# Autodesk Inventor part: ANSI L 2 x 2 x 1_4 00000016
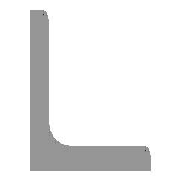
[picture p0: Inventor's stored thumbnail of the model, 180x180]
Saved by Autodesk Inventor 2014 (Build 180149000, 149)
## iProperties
IsCustomPart: 1
Created: 2007-02
Part Number: ANSI L 2 x 2 x 1_4 00000016
Material: Steel, Mild
Document SubType Name: Modeling
Standard: AISC
Designer: Autodesk, Inc.
Size Designation: L 2 x 2 x 1/4
Stock Number: L 2 x 2 x 1/4
Density: 7.86 g/cm^3
Description: Angle Steel
Standards Organization: ANSI
Language: en-US
Categories: <MemberInstance><Categories><Category DisplayName="Structural Shapes" InternalName="089c4875-fa83-4c05-b084-43b9cc11f5ed" Mnemonic="GRDR"><CategoryParameter Dis
Mass: 1510.44 g
Surface Area: 652.682 cm^2
Volume: 192.168 cm^3
Appearance: Steel
_FrameMemberDoc: Frame Member File
_Version: 15.0.0
_CCFamilyMember: 11
_CCFamilyDisplayName: ANSI L (Equal angles) - Angle Steel
G_L: 14.750 in
G_W: 2.000 in
G_H: 2.000 in
+8C4DC5A2-1CB2-4683-A8ED-186AF0FDBA7E+CUTDETAIL1: Notch
+BEC1791F-D03F-4A56-8F25-61346F2A3048+CUTDETAIL2: Notch
Author: Autodesk, Inc.
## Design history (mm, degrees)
node "Start plane"
node "End plane"
sketch "Sketch"
  geometry: L1 (50.8, 0)-(0, 0); L2 (0, 0)-(0, 50.8); L3 (0, 50.8)-(3.302, 50.8); L4 (6.35, 47.752)-(6.35, 12.7); L5 (12.7, 6.35)-(47.752, 6.35); L6 (50.8, 3.302)-(50.8, 0); L7 (0, -11.041)-(0, 31.538); L8 (-11.041, 0)-(31.538, 0); L9 (0, 63.926)-(0, -23.536) reference; L10 (-23.536, 0)-(63.926, 0) reference; A1 r 6.35 centre (12.7, 12.7) between (6.35, 12.7) and (12.7, 6.35); A2 r 3.048 centre (3.302, 47.752) between (6.35, 47.752) and (3.302, 50.8); A3 r 3.048 centre (47.752, 3.302) between (50.8, 3.302) and (47.752, 6.35); 3 further points
  constraints: 16 end point, 6 point on circle, 6 point on line, 6 tangent, 4 parallel, 3 centre point, 2 collinear, 1 equal radius, 1 horizontal, 1 perpendicular
  dimensions: "d0" = 50.8 distance between parallel lines of L6 L2 (= G_H); "d1" = 50.8 distance between parallel lines of L3 L1 (= G_H); "d2" = 6.35 distance between parallel lines of L2 L4 (= G_T); "d3" = 6.35 distance between parallel lines of L1 L5 (= G_T); "d10" = 0 distance between parallel lines of L7 L2 (computed from ex); "d11" = 0 distance between parallel lines of L8 L1 (computed from d10); "d14" = 6.35 radius of A1 (= G_IR); "d15" = 3.048 radius of A2 (= G_ER)
extrude "Body" new body sketch "Sketch" stored distance "d4" = 374.65 (= G_L); taper "d5" = 0 deg
node "Driven Length"
  sketch "Sketch5"
    geometry: L1 (0, 0)-(10, 0) reference
    constraints: 2 end point, 1 horizontal
  workplane "Work Plane7"
  sketch "Sketch6"
    geometry: L1 (-2, 0)-(12, 0) reference; L2 (-2, 374.65)-(12, 374.65) reference
    dimensions: "d21" = 374.65 distance between parallel lines of L1 L2 (derived)
workplane "Work Plane3"
workplane "Work Plane4"
workplane "Work Plane5"
workplane "Work Plane6"
workplane "Work Plane8"
workplane "Work Plane9"
body "Solid1"
sketch "Sketch_3"
  geometry: L1 (50.8, 0)-(0, 0); L2 (0, 0)-(0, 50.8); L3 (0, 50.8)-(3.302, 50.8); L4 (6.35, 47.752)-(6.35, 12.7); L5 (12.7, 6.35)-(47.752, 6.35); L6 (50.8, 3.302)-(50.8, 0); A1 r 3.048 centre (3.302, 47.752) between (6.35, 47.752) and (3.302, 50.8); A2 r 6.35 centre (12.7, 12.7) between (6.35, 12.7) and (12.7, 6.35); A3 r 3.048 centre (47.752, 3.302) between (50.8, 3.302) and (47.752, 6.35)
  constraints: 12 end point, 6 point on circle, 3 centre point
extrude "Extrusion2" cut sketch "Sketch_3" stored distance "d22" = 3.302; taper "d23" = 0 deg
sketch "Sketch_1"
  geometry: L1 (50.8, 0)-(0, 0); L2 (0, 0)-(0, 50.8); L3 (0, 50.8)-(3.302, 50.8); L4 (6.35, 47.752)-(6.35, 12.7); L5 (12.7, 6.35)-(47.752, 6.35); L6 (50.8, 3.302)-(50.8, 0); A1 r 3.048 centre (3.302, 47.752) between (6.35, 47.752) and (3.302, 50.8); A2 r 6.35 centre (12.7, 12.7) between (6.35, 12.7) and (12.7, 6.35); A3 r 3.048 centre (47.752, 3.302) between (50.8, 3.302) and (47.752, 6.35)
  constraints: 12 end point, 6 point on circle, 3 centre point
extrude "Extrusion3" cut sketch "Sketch_1" stored distance "d24" = 3.302; taper "d25" = 0 deg
other parameters: "G_H" = 50.8 [user parameter; used in 2 equation terms], "G_T" = 6.35 [user parameter; used in 2 equation terms], "G_ER" = 3.048 [user parameter; used in 1 equation term], "G_IR" = 6.35 [user parameter; used in 1 equation term], "G_L" = 374.65 (= d21) [user parameter; used in 1 equation term], "ex" = 0 [user parameter; used in 1 equation term], "G_OFFSET_START" = 0 [user parameter; used in 1 equation term], "G_OFFSET_END" = 0 [user parameter; used in 1 equation term], "d12" = 0 (computed from G_OFFSET_START), "d13" = 374.65 (= G_OFFSET_END + B_L), "B_L" = 374.65 [user parameter; used in 1 equation term], "d20" = 90 deg
